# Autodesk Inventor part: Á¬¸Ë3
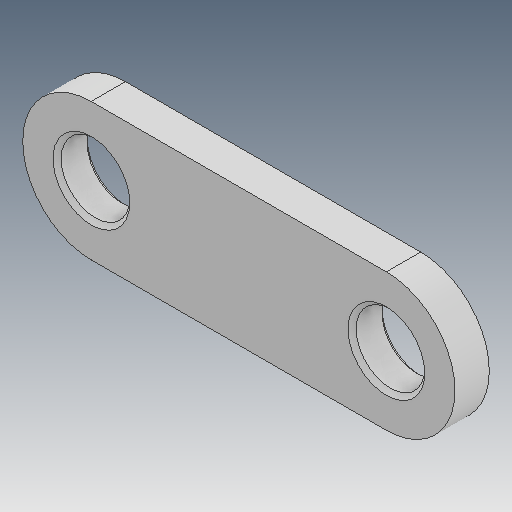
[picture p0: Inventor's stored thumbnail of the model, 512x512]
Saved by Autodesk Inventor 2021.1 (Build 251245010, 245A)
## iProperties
Created: 2013-04
Part Number: Á¬¸Ë3
Material: Ogólny
Document SubType Name: Modeling
Designer: user
Density: 1 g/cm^3
Appearance: Domyślna
Author: user
Revision Number: ÈÎºÎ
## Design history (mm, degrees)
feature "µ¹½Ç1"
node "Bryła1"
